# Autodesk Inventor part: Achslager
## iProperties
Created: 2008-01
Part Number: Achslager
Document SubType Name: Modeling
Designer: Mathemaster
Author: Mathemaster
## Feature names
1. Extrusion1
2. Extrusion3
3. Extrusion4
4. Extrusion5
5. Drehung3 [Revolution]
6. Drehung5 [Revolution]
7. Drehung6 [Revolution]
8. Extrusion8
9. Extrusion10
10. Extrusion11
11. Extrusion12
12. Extrusion13
13. Extrusion14
14. Extrusion15
15. Extrusion16
16. Extrusion17
17. Extrusion18
18. Extrusion19
19. Extrusion21
20. Extrusion22
21. Extrusion23
22. Extrusion24
23. Extrusion25
24. Extrusion26
25. Extrusion27
26. Extrusion28
